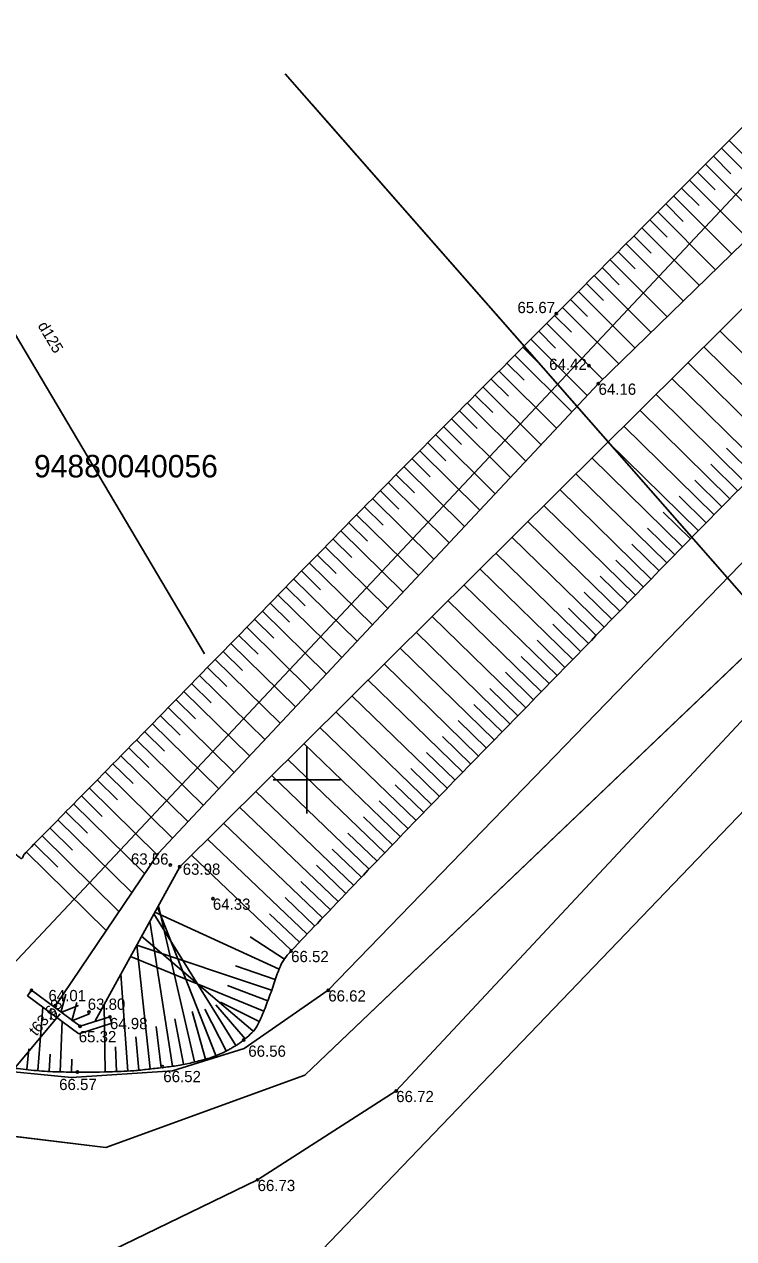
# Model space of a CAD drawing. Extents: x 616607 to 617499, y 408385 to 409695.
# Drawn here: x 617337.4 to 617369, y 409529.6 to 409583.6 of the extents above; entities that cross this region are included whole.
import ezdxf

# ---------------------------------------------------------------- set-up
doc = ezdxf.new("R2010")
doc.units = 0
for name, color, linetype in [('BUVE_BDET_####_####_#', 7, 'Continuous'), ('BUVE_BDET_####_TKST_#', 7, 'Continuous'), ('CELI_CMAL_####_####_#', 7, 'Continuous'), ('DREN_VADP_####_####_#', 7, 'Continuous'), ('DREN_VADP_####_TKST_#', 7, 'Continuous'), ('GEOD_ELEM_####_####_#', 7, 'Continuous'), ('HIDG_GRAV_####_####_#', 7, 'Continuous'), ('HIDT_CAUR_####_####_#', 7, 'Continuous'), ('HIDT_CAUR_####_TKST_#', 7, 'Continuous'), ('HIDT_ELEM_####_####_#', 7, 'Continuous'), ('RAMI_UZMR_####_####_#', 7, 'Continuous'), ('RELJ_AATZ_####_TKST_#', 7, 'Continuous'), ('RELJ_ELEM_####_####_#', 7, 'Continuous'), ('RELJ_NOGA_####_####_#', 7, 'Continuous'), ('ROBZ_IERR_####_####_#', 7, 'Continuous'), ('ROBZ_IERR_####_TKST_#', 7, 'Continuous'), ('ROBZ_UZMR_####_####_#', 7, 'Continuous')]:
    doc.layers.add(name, color=color, linetype=linetype)

# ---------------------------------------------------------------- blocks, each defined once
blk = doc.blocks.new('PKT')
at = {"layer": 'RELJ_ELEM_####_####_#'}
blk.add_circle((0, 0), 0.05, dxfattribs=at)
blk = doc.blocks.new('CAURT')
at = {"layer": 'HIDT_ELEM_####_####_#'}
blk.add_lwpolyline([(0.75, -0.374), (0, 0), (0.75, 0.376)], dxfattribs=at)
blk = doc.blocks.new('KRUSTS')
at = {"layer": 'GEOD_ELEM_####_####_#'}
for p, q in [((0, 1.5), (0, 0)), ((-1.5, 0), (0, 0)), ((0, 0), (0, -1.5)), ((0, 0), (1.5, 0))]:
    blk.add_line(p, q, dxfattribs=at)

msp = doc.modelspace()

# ---------------------------------------------------------------- linework, layer by layer
at = {"layer": 'BUVE_BDET_####_####_#'}
for p, q in [((617337.749, 409540.638), (617337.571, 409540.397)), ((617337.571, 409540.397), (617339.855, 409538.707)), ((617339.855, 409538.707), (617341.33, 409539.173)), ((617341.239, 409539.459), (617341.33, 409539.173))]:
    msp.add_line(p, q, dxfattribs=at)
for points in [[(617337.749, 409540.638), (617339.911, 409539.039)], [(617339.911, 409539.039), (617341.239, 409539.459)]]:
    msp.add_lwpolyline(points, dxfattribs=at)
at = {"layer": 'CELI_CMAL_####_####_#'}
for points in [[(617432.033, 409621.181), (617371.58, 409561.929), (617350.956, 409540.638)], [(617336.893, 409526.922), (617347.811, 409532.207), (617353.979, 409536.163), (617374.992, 409558.661), (617435.286, 409617.887)], [(617329.129, 409540.872), (617335.578, 409537.138), (617339.527, 409536.758), (617344.023, 409537.049), (617347.209, 409538.054), (617350.956, 409540.638)]]:
    msp.add_lwpolyline(points, dxfattribs=at)
at = {"layer": 'DREN_VADP_####_####_#'}
msp.add_lwpolyline([(617345.447, 409555.599), (617333.219, 409576.192)], dxfattribs=at)
at = {"layer": 'HIDG_GRAV_####_####_#'}
for points in [[(617338.767, 409539.885), (617343.397, 409546.74), (617362.983, 409567.623), (617407.627, 409611.031), (617419.903, 409623.142)], [(617340.575, 409539.249), (617344.345, 409546.134), (617420.843, 409621.996)]]:
    msp.add_lwpolyline(points, dxfattribs=at)
at = {"layer": 'HIDT_CAUR_####_####_#'}
msp.add_lwpolyline([(617328.298, 409526.812), (617339.023, 409539.598)], dxfattribs=at)
at = {"layer": 'RAMI_UZMR_####_####_#'}
msp.add_lwpolyline([(617101.571, 408748.246), (617213.472, 409074.039), (617215.883, 409140.56), (617165.121, 409241.478), (617252.137, 409353.424), (617269.572, 409425.099), (617332.631, 409510.312), (617439.945, 409622.037), (617425.373, 409635.959), (617242.079, 409440.82), (617216.614, 409355.716), (617136.613, 409246.751), (617191.828, 409115.62), (617145.545, 408952.8)], dxfattribs=at)
at = {"layer": 'RELJ_NOGA_####_####_#'}
for p, q in [((617368.446, 409578.086), (617371.059, 409575.476)), ((617368.446, 409578.086), (617368.447, 409578.085)), ((617368.8, 409578.44), (617369.585, 409577.655)), ((617368.8, 409578.44), (617368.8, 409578.439)), ((617368.093, 409577.732), (617368.875, 409576.951)), ((617368.093, 409577.732), (617368.093, 409577.732)), ((617367.386, 409577.025), (617368.165, 409576.246)), ((617367.386, 409577.025), (617367.386, 409577.024)), ((617367.74, 409577.378), (617370.342, 409574.779)), ((617367.74, 409577.378), (617367.74, 409577.378)), ((617367.033, 409576.671), (617369.625, 409574.082)), ((617367.033, 409576.671), (617367.034, 409576.67)), ((617366.326, 409575.963), (617368.908, 409573.384)), ((617366.326, 409575.963), (617366.327, 409575.963)), ((617366.679, 409576.317), (617367.455, 409575.542)), ((617366.679, 409576.317), (617366.68, 409576.317)), ((617365.973, 409575.61), (617366.746, 409574.838)), ((617365.973, 409575.61), (617365.973, 409575.609)), ((617365.266, 409574.902), (617366.036, 409574.133)), ((617365.266, 409574.902), (617365.266, 409574.902)), ((617365.619, 409575.256), (617368.191, 409572.687)), ((617365.619, 409575.256), (617365.62, 409575.255)), ((617364.559, 409574.195), (617365.326, 409573.429)), ((617364.559, 409574.195), (617364.559, 409574.194)), ((617364.913, 409574.548), (617367.474, 409571.99)), ((617364.913, 409574.548), (617364.913, 409574.548)), ((617364.206, 409573.841), (617366.757, 409571.293)), ((617364.206, 409573.841), (617364.207, 409573.84)), ((617363.499, 409573.133), (617366.04, 409570.596)), ((617363.499, 409573.133), (617363.5, 409573.133)), ((617363.853, 409573.487), (617364.616, 409572.724)), ((617363.853, 409573.487), (617363.853, 409573.487)), ((617363.146, 409572.78), (617363.906, 409572.02)), ((617363.146, 409572.78), (617363.146, 409572.78)), ((617362.439, 409572.072), (617363.197, 409571.316)), ((617362.439, 409572.072), (617362.439, 409572.072)), ((617362.792, 409572.426), (617365.322, 409569.899)), ((617362.792, 409572.426), (617362.793, 409572.425)), ((617362.086, 409571.719), (617364.605, 409569.201)), ((617362.086, 409571.719), (617362.086, 409571.718)), ((617361.379, 409571.011), (617363.888, 409568.504)), ((617361.379, 409571.011), (617361.38, 409571.01)), ((617361.732, 409571.365), (617362.487, 409570.611)), ((617361.732, 409571.365), (617361.733, 409571.365)), ((617361.026, 409570.657), (617361.777, 409569.907)), ((617361.026, 409570.657), (617361.026, 409570.657)), ((617360.319, 409569.949), (617361.071, 409569.201)), ((617360.319, 409569.949), (617360.319, 409569.949)), ((617360.672, 409570.303), (617363.172, 409567.808)), ((617360.672, 409570.303), (617360.673, 409570.303)), ((617372.335, 409566.063), (617368.377, 409569.966)), ((617359.966, 409569.595), (617362.481, 409567.089)), ((617359.966, 409569.595), (617359.967, 409569.595)), ((617359.261, 409568.887), (617361.799, 409566.361)), ((617359.261, 409568.887), (617359.261, 409568.886)), ((617359.613, 409569.241), (617360.372, 409568.487)), ((617359.613, 409569.241), (617359.614, 409569.241)), ((617371.633, 409565.351), (617367.667, 409569.262)), ((617358.908, 409568.532), (617359.673, 409567.772)), ((617358.908, 409568.532), (617358.908, 409568.532)), ((617370.931, 409564.639), (617366.955, 409568.556)), ((617358.203, 409567.823), (617358.975, 409567.057)), ((617358.203, 409567.823), (617358.203, 409567.823)), ((617358.556, 409568.177), (617361.116, 409565.633)), ((617358.556, 409568.177), (617358.556, 409568.177)), ((617370.229, 409563.926), (617366.245, 409567.852)), ((617357.851, 409567.468), (617360.433, 409564.905)), ((617357.851, 409567.468), (617357.852, 409567.467)), ((617357.147, 409566.758), (617359.751, 409564.177)), ((617357.147, 409566.758), (617357.148, 409566.757)), ((617357.499, 409567.113), (617358.277, 409566.342)), ((617357.499, 409567.113), (617357.499, 409567.113)), ((617369.527, 409563.214), (617365.533, 409567.146)), ((617356.795, 409566.403), (617357.58, 409565.626)), ((617356.795, 409566.403), (617356.795, 409566.402)), ((617368.826, 409562.501), (617364.823, 409566.442)), ((617356.092, 409565.692), (617356.882, 409564.91)), ((617356.092, 409565.692), (617356.092, 409565.691)), ((617356.443, 409566.047), (617359.068, 409563.449)), ((617356.443, 409566.047), (617356.444, 409566.046)), ((617368.125, 409561.788), (617364.11, 409565.735)), ((617355.74, 409565.336), (617358.385, 409562.721)), ((617355.74, 409565.336), (617355.741, 409565.335)), ((617367.424, 409561.074), (617363.395, 409565.026)), ((617355.037, 409564.625), (617357.703, 409561.994)), ((617355.037, 409564.625), (617355.038, 409564.624)), ((617355.389, 409564.981), (617356.185, 409564.193)), ((617355.389, 409564.981), (617355.389, 409564.98)), ((617369.878, 409563.57), (617368.681, 409564.749)), ((617354.686, 409564.269), (617355.489, 409563.477)), ((617354.686, 409564.269), (617354.686, 409564.269)), ((617366.724, 409560.36), (617362.682, 409564.319)), ((617369.177, 409562.857), (617367.977, 409564.038)), ((617353.984, 409563.557), (617354.792, 409562.76)), ((617353.984, 409563.557), (617353.984, 409563.557)), ((617354.335, 409563.913), (617357.019, 409561.264)), ((617354.335, 409563.913), (617354.336, 409563.912)), ((617366.025, 409559.646), (617361.969, 409563.612)), ((617353.633, 409563.201), (617356.336, 409560.537)), ((617353.633, 409563.201), (617353.633, 409563.2)), ((617365.326, 409558.93), (617361.256, 409562.905)), ((617368.475, 409562.145), (617367.272, 409563.327)), ((617352.931, 409562.489), (617355.653, 409559.809)), ((617352.931, 409562.489), (617352.932, 409562.488)), ((617353.282, 409562.845), (617354.095, 409562.043)), ((617353.282, 409562.845), (617353.282, 409562.845)), ((617367.774, 409561.431), (617366.567, 409562.615)), ((617352.229, 409561.776), (617354.969, 409559.079)), ((617352.229, 409561.776), (617352.23, 409561.775)), ((617352.58, 409562.132), (617353.399, 409561.326)), ((617352.58, 409562.132), (617352.58, 409562.132)), ((617364.627, 409558.215), (617360.546, 409562.201)), ((617367.074, 409560.717), (617365.864, 409561.904)), ((617351.879, 409561.42), (617352.704, 409560.608)), ((617351.879, 409561.42), (617351.879, 409561.419)), ((617363.929, 409557.499), (617359.833, 409561.493)), ((617351.178, 409560.707), (617352.007, 409559.89)), ((617351.178, 409560.707), (617351.178, 409560.706)), ((617351.528, 409561.063), (617354.286, 409558.351)), ((617351.528, 409561.063), (617351.529, 409561.062)), ((617363.231, 409556.783), (617359.123, 409560.789)), ((617366.375, 409560.003), (617365.16, 409561.192)), ((617350.827, 409560.35), (617353.603, 409557.623)), ((617350.827, 409560.35), (617350.828, 409560.349)), ((617365.675, 409559.288), (617364.457, 409560.48)), ((617350.126, 409559.637), (617352.919, 409556.893)), ((617350.126, 409559.637), (617350.127, 409559.636)), ((617350.477, 409559.993), (617351.312, 409559.173)), ((617350.477, 409559.993), (617350.477, 409559.993)), ((617362.533, 409556.067), (617358.413, 409560.085)), ((617364.977, 409558.573), (617363.754, 409559.767)), ((617349.776, 409559.28), (617350.616, 409558.454)), ((617349.776, 409559.28), (617349.776, 409559.28)), ((617361.835, 409555.351), (617357.703, 409559.381)), ((617349.075, 409558.566), (617349.921, 409557.737)), ((617349.075, 409558.566), (617349.076, 409558.566)), ((617349.426, 409558.923), (617352.236, 409556.165)), ((617349.426, 409558.923), (617349.426, 409558.923)), ((617361.136, 409554.635), (617356.992, 409558.676)), ((617364.278, 409557.857), (617363.051, 409559.054)), ((617348.725, 409558.209), (617351.552, 409555.436)), ((617348.725, 409558.209), (617348.726, 409558.209)), ((617363.58, 409557.141), (617362.349, 409558.341)), ((617348.025, 409557.496), (617350.868, 409554.706)), ((617348.025, 409557.496), (617348.026, 409557.495)), ((617348.375, 409557.853), (617349.225, 409557.018)), ((617348.375, 409557.853), (617348.375, 409557.852)), ((617360.438, 409553.919), (617356.282, 409557.972)), ((617362.882, 409556.425), (617361.648, 409557.629)), ((617347.675, 409557.139), (617348.53, 409556.3)), ((617347.675, 409557.139), (617347.675, 409557.139)), ((617359.74, 409553.204), (617355.574, 409557.27)), ((617362.184, 409555.709), (617360.946, 409556.916)), ((617346.975, 409556.425), (617347.835, 409555.581)), ((617346.975, 409556.425), (617346.975, 409556.424)), ((617347.325, 409556.782), (617350.185, 409553.977)), ((617347.325, 409556.782), (617347.325, 409556.781)), ((617359.041, 409552.488), (617354.864, 409556.566)), ((617346.625, 409556.068), (617349.5, 409553.248)), ((617346.625, 409556.068), (617346.625, 409556.067)), ((617358.343, 409551.772), (617354.153, 409555.861)), ((617361.485, 409554.993), (617360.244, 409556.204)), ((617345.924, 409555.354), (617348.816, 409552.518)), ((617345.924, 409555.354), (617345.925, 409555.353)), ((617346.274, 409555.711), (617347.14, 409554.862)), ((617346.274, 409555.711), (617346.275, 409555.71)), ((617360.787, 409554.277), (617359.542, 409555.491)), ((617345.574, 409554.997), (617346.444, 409554.144)), ((617345.574, 409554.997), (617345.575, 409554.996)), ((617357.645, 409551.056), (617353.439, 409555.153)), ((617360.089, 409553.562), (617358.841, 409554.78)), ((617344.874, 409554.283), (617345.749, 409553.425)), ((617344.874, 409554.283), (617344.874, 409554.282)), ((617345.224, 409554.64), (617348.132, 409551.789)), ((617345.224, 409554.64), (617345.225, 409554.639)), ((617356.948, 409550.339), (617352.723, 409554.442)), ((617344.524, 409553.926), (617347.448, 409551.059)), ((617344.524, 409553.926), (617344.525, 409553.925)), ((617356.251, 409549.622), (617352.009, 409553.734)), ((617359.391, 409552.846), (617358.139, 409554.067)), ((617343.824, 409553.212), (617346.763, 409550.33)), ((617343.824, 409553.212), (617343.825, 409553.211)), ((617344.174, 409553.569), (617345.054, 409552.706)), ((617344.174, 409553.569), (617344.174, 409553.568)), ((617358.692, 409552.13), (617357.437, 409553.355)), ((617343.474, 409552.855), (617344.358, 409551.988)), ((617343.474, 409552.855), (617343.474, 409552.854)), ((617355.555, 409548.904), (617351.295, 409553.026)), ((617357.994, 409551.414), (617356.734, 409552.642)), ((617342.774, 409552.141), (617343.663, 409551.269)), ((617342.774, 409552.141), (617342.774, 409552.14)), ((617343.124, 409552.498), (617346.079, 409549.6)), ((617343.124, 409552.498), (617343.125, 409552.497)), ((617354.86, 409548.185), (617350.581, 409552.319)), ((617342.424, 409551.784), (617345.394, 409548.87)), ((617342.424, 409551.784), (617342.424, 409551.783)), ((617354.166, 409547.465), (617349.868, 409551.611)), ((617357.296, 409550.698), (617356.032, 409551.928)), ((617341.723, 409551.07), (617344.71, 409548.14)), ((617341.723, 409551.07), (617341.724, 409551.069)), ((617342.074, 409551.427), (617342.967, 409550.55)), ((617342.074, 409551.427), (617342.074, 409551.426)), ((617356.599, 409549.981), (617355.33, 409551.214)), ((617341.373, 409550.713), (617342.271, 409549.831)), ((617341.373, 409550.713), (617341.373, 409550.713)), ((617353.472, 409546.745), (617349.154, 409550.903)), ((617355.903, 409549.263), (617354.628, 409550.498)), ((617340.673, 409549.999), (617341.576, 409549.113)), ((617340.673, 409549.999), (617340.673, 409549.999)), ((617341.023, 409550.356), (617344.025, 409547.409)), ((617341.023, 409550.356), (617341.024, 409550.355)), ((617352.779, 409546.024), (617348.439, 409550.194)), ((617340.322, 409549.642), (617343.349, 409546.669)), ((617340.322, 409549.642), (617340.323, 409549.642)), ((617352.086, 409545.303), (617347.725, 409549.486)), ((617355.208, 409548.544), (617353.927, 409549.783)), ((617339.622, 409548.929), (617342.78, 409545.826)), ((617339.622, 409548.929), (617339.622, 409548.928)), ((617339.972, 409549.286), (617340.9, 409548.374)), ((617339.972, 409549.286), (617339.972, 409549.286)), ((617354.513, 409547.825), (617353.226, 409549.067)), ((617339.271, 409548.573), (617340.238, 409547.622)), ((617339.271, 409548.573), (617339.271, 409548.572)), ((617351.395, 409544.581), (617347.009, 409548.776)), ((617353.819, 409547.105), (617352.526, 409548.35)), ((617338.57, 409547.859), (617339.576, 409546.869)), ((617338.57, 409547.859), (617338.57, 409547.859)), ((617338.921, 409548.216), (617342.209, 409544.981)), ((617338.921, 409548.216), (617338.921, 409548.215)), ((617350.704, 409543.858), (617346.295, 409548.068)), ((617338.219, 409547.503), (617341.639, 409544.138)), ((617338.219, 409547.503), (617338.22, 409547.502)), ((617350.013, 409543.134), (617345.581, 409547.36)), ((617353.125, 409546.385), (617351.826, 409547.633)), ((617337.518, 409546.79), (617341.07, 409543.295)), ((617337.518, 409546.79), (617337.519, 409546.79)), ((617337.869, 409547.147), (617338.915, 409546.118)), ((617337.869, 409547.147), (617337.869, 409547.146)), ((617349.324, 409542.41), (617344.867, 409546.652)), ((617352.432, 409545.664), (617351.128, 409546.917)), ((617351.74, 409544.942), (617350.428, 409546.199)), ((617351.049, 409544.219), (617349.73, 409545.481)), ((617350.358, 409543.496), (617349.032, 409544.761)), ((617346.849, 409538.185), (617343.195, 409544.033)), ((617348.773, 409541.582), (617343.236, 409544.109)), ((617345.958, 409537.734), (617343.359, 409544.334)), ((617345, 409537.451), (617343.395, 409544.399)), ((617349.669, 409542.772), (617348.335, 409544.042)), ((617344.018, 409537.263), (617343.016, 409543.708)), ((617347.606, 409538.832), (617342.65, 409543.039)), ((617349.012, 409542.02), (617347.485, 409543.022)), ((617343.026, 409537.138), (617342.433, 409542.642)), ((617348.435, 409540.641), (617342.437, 409542.65)), ((617348.084, 409539.704), (617342.157, 409542.138)), ((617342.03, 409537.048), (617341.732, 409541.362)), ((617348.595, 409541.115), (617346.827, 409541.721)), ((617348.265, 409540.171), (617346.478, 409540.844)), ((617338.033, 409537.072), (617338.255, 409539.891)), ((617341.031, 409537.005), (617340.977, 409539.983)), ((617345.485, 409537.573), (617344.898, 409539.695)), ((617346.414, 409537.939), (617345.466, 409539.8)), ((617347.252, 409538.48), (617345.948, 409539.988)), ((617347.884, 409539.246), (617346.162, 409540.106)), ((617339.031, 409537.015), (617339.11, 409539.258)), ((617344.511, 409537.348), (617344.123, 409539.366)), ((617342.529, 409537.088), (617342.396, 409538.564)), ((617343.523, 409537.195), (617343.304, 409539.026)), ((617337.535, 409537.115), (617337.627, 409538.04)), ((617341.531, 409537.021), (617341.482, 409538.124)), ((617338.532, 409537.039), (617338.575, 409537.801)), ((617339.531, 409537.003), (617339.539, 409537.58)), ((617337.535, 409537.115), (617337.535, 409537.116)), ((617337.535, 409537.113), (617337.535, 409537.113)), ((617338.033, 409537.072), (617338.033, 409537.073)), ((617338.033, 409537.07), (617338.033, 409537.071)), ((617338.532, 409537.038), (617338.532, 409537.039)), ((617338.532, 409537.039), (617338.532, 409537.039)), ((617339.031, 409537.015), (617339.031, 409537.016)), ((617339.032, 409537.016), (617339.032, 409537.017)), ((617339.531, 409537.004), (617339.531, 409537.004)), ((617339.531, 409537.003), (617339.531, 409537.003)), ((617340.031, 409536.999), (617340.031, 409537)), ((617340.031, 409536.999), (617340.031, 409537)), ((617340.531, 409536.999), (617340.531, 409536.999)), ((617340.531, 409536.999), (617340.531, 409536.999))]:
    msp.add_line(p, q, dxfattribs=at)
for points in [[(617340.777, 409537.001), (617341.078, 409537.005), (617341.378, 409537.016), (617341.678, 409537.028), (617342.308, 409537.052), (617342.934, 409537.126), (617343.561, 409537.2), (617344.196, 409537.274), (617344.821, 409537.394), (617345.442, 409537.561), (617345.753, 409537.644), (617346.049, 409537.762), (617346.339, 409537.902), (617346.489, 409537.973), (617346.63, 409538.054), (617346.772, 409538.138), (617346.919, 409538.225), (617347.057, 409538.319), (617347.191, 409538.428), (617347.493, 409538.675), (617347.758, 409538.966), (617347.918, 409539.317), (617348.078, 409539.667), (617348.21, 409540.021), (617348.343, 409540.379), (617348.475, 409540.736), (617348.579, 409541.101), (617348.72, 409541.456), (617348.856, 409541.799), (617349.051, 409542.123), (617349.304, 409542.39), (617352.519, 409545.77), (617355.747, 409549.116), (617359.001, 409552.447), (617362.259, 409555.782), (617365.506, 409559.128), (617368.776, 409562.45), (617375.323, 409569.103), (617381.891, 409575.733), (617388.441, 409582.383), (617394.992, 409589.035), (617401.535, 409595.694), (617408.065, 409602.367), (617411.328, 409605.701), (617414.56, 409609.066), (617417.789, 409612.434), (617421.016, 409615.8), (617424.21, 409619.196), (617427.415, 409622.582), (617427.788, 409622.976), (617428.152, 409623.378), (617428.521, 409623.775), (617428.615, 409623.876), (617428.734, 409623.953), (617428.829, 409624.052), (617428.856, 409624.08), (617428.859, 409624.145), (617428.829, 409624.171), (617428.532, 409624.429), (617428.227, 409624.676), (617427.914, 409624.914), (617427.604, 409625.151), (617427.298, 409625.391), (617426.983, 409625.621), (617426.355, 409626.078), (617425.721, 409626.524), (617425.072, 409626.95), (617424.42, 409627.378), (617423.762, 409627.796), (617423.101, 409628.211), (617422.43, 409628.633), (617421.754, 409629.042), (617421.074, 409629.457), (617420.952, 409629.531), (617420.825, 409629.61), (617420.7, 409629.662), (617420.6, 409629.703), (617420.471, 409629.604), (617420.39, 409629.526), (617415.561, 409624.878), (617410.732, 409620.23), (617405.903, 409615.582)], [(617405.903, 409615.582), (617390.969, 409600.632), (617376.035, 409585.682), (617361.1, 409570.732), (617353.162, 409562.786), (617345.334, 409554.728), (617337.455, 409546.726), (617337.388, 409546.658), (617337.328, 409546.458), (617337.253, 409546.519), (617336.529, 409547.109), (617335.804, 409547.698), (617335.079, 409548.288)], [(617331.056, 409543.191), (617332.054, 409541.542), (617333.052, 409539.893), (617334.051, 409538.243), (617334.188, 409538.016), (617334.501, 409537.961), (617334.744, 409537.85), (617334.977, 409537.743), (617335.205, 409537.638), (617335.447, 409537.552), (617335.916, 409537.385), (617336.387, 409537.247), (617336.878, 409537.187), (617337.849, 409537.069), (617338.82, 409537.003), (617339.794, 409537), (617340.122, 409536.999), (617340.45, 409536.997), (617340.777, 409537.001)]]:
    msp.add_open_spline(points, degree=3, dxfattribs=at)
at = {"layer": 'ROBZ_IERR_####_####_#'}
for points in [[(617368.929, 409601.756), (617389.961, 409575.652), (617384.525, 409570.278), (617370.73, 409556.7), (617349.038, 409581.404)], [(617350.237, 409580.038), (617370.73, 409556.7), (617349.913, 409536.856), (617341.051, 409533.641), (617335.391, 409534.333), (617330.95, 409541.554), (617324.668, 409549.301)]]:
    msp.add_lwpolyline(points, dxfattribs=at)
at = {"layer": 'ROBZ_UZMR_####_####_#'}
msp.add_lwpolyline([(617232.583, 409073.745), (617196.025, 409075.262), (617200.886, 409119.423), (617196.507, 409136.07), (617150.138, 409230.13), (617148.652, 409247.272), (617201.229, 409318.934), (617233.453, 409357.938), (617244.928, 409391.934), (617250.98, 409414.497), (617255.789, 409432.426), (617326.39, 409521.291), (617332.188, 409529.592), (617332.358, 409529.835), (617335.391, 409534.333), (617341.051, 409533.641), (617349.913, 409536.856), (617370.73, 409556.7), (617378.749, 409547.935), (617381.343, 409545.1)], dxfattribs=at)

# ---------------------------------------------------------------- block references
at = {"layer": 'GEOD_ELEM_####_####_#'}
msp.add_blockref('KRUSTS', (617350, 409550), dxfattribs=at)
at = {"layer": 'HIDT_ELEM_####_####_#', "rotation": 47.95838634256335}
for p in [(617339.058, 409539.655), (617339.545, 409539.284)]:
    msp.add_blockref('CAURT', p, dxfattribs=at)
at = {"layer": 'RELJ_ELEM_####_####_#'}
for p in [(617361.1, 409570.732), (617362.555, 409568.42), (617362.973, 409567.617), (617343.927, 409546.21), (617344.345, 409546.134), (617345.821, 409544.718), (617349.304, 409542.39), (617337.749, 409540.638), (617350.956, 409540.638), (617338.815, 409539.956), (617340.307, 409539.67), (617339.911, 409539.039), (617341.239, 409539.459), (617347.191, 409538.428), (617339.794, 409537), (617343.575, 409537.242), (617353.979, 409536.163), (617347.811, 409532.207)]:
    msp.add_blockref('PKT', p, dxfattribs=at)

# ---------------------------------------------------------------- texts
at = {"layer": 'BUVE_BDET_####_TKST_#'}
msp.add_text('b', height=0.5, dxfattribs=at).set_placement((617338.547, 409539.32))
at = {"layer": 'DREN_VADP_####_TKST_#'}
msp.add_text('d125', height=0.5, rotation=300.6999, dxfattribs=at).set_placement((617338.007, 409570.2))
at = {"layer": 'HIDT_CAUR_####_TKST_#'}
msp.add_text('t63.63', height=0.5, rotation=50.0102, dxfattribs=at).set_placement((617337.966, 409538.572))
at = {"layer": 'RELJ_AATZ_####_TKST_#'}
for s, p in [('65.67', (617359.375, 409570.755)), ('64.42', (617360.786, 409568.227)), ('64.16', (617362.983, 409567.123)), ('63.56', (617342.174, 409546.227)), ('63.98', (617344.479, 409545.775)), ('64.33', (617345.821, 409544.218)), ('66.52', (617349.304, 409541.89)), ('64.01', (617338.504, 409540.153)), ('63.80', (617340.252, 409539.769)), ('66.62', (617350.956, 409540.138)), ('64.98', (617341.239, 409538.909)), ('65.32', (617339.851, 409538.326)), ('66.56', (617347.398, 409537.681)), ('66.52', (617343.615, 409536.551)), ('66.57', (617338.981, 409536.201)), ('66.72', (617353.979, 409535.663)), ('66.73', (617347.811, 409531.707))]:
    msp.add_text(s, height=0.5, dxfattribs=at).set_placement(p)
at = {"layer": 'ROBZ_IERR_####_TKST_#'}
msp.add_text('94880040056', height=1, dxfattribs=at).set_placement((617337.862, 409563.449))

doc.saveas('drawing.dxf')
